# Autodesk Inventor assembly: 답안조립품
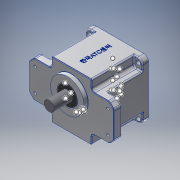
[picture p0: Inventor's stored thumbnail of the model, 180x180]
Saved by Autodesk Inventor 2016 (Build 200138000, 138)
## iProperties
Created: 2017-01
Part Number: 답안조립품
Material: 일반
Document SubType Name: Assembly
Designer: Owner
Author: Owner
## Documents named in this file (10)
- C:\Users\Owner\Desktop\470111V1013\답안조립품.iam
- C:\Users\Owner\Desktop\470111V1013\본체.ipt
- C:\Users\Owner\Desktop\470111V1013\메인축.ipt
- C:\Users\Owner\Desktop\470111V1013\베어링 608.ipt
- C:\Users\Owner\Desktop\470111V1013\베어링 6003.ipt
- C:\Users\Owner\Desktop\470111V1013\볼트 M4 x 10.ipt
- C:\Users\Owner\Desktop\470111V1013\서브축.ipt
- C:\Users\Owner\Desktop\470111V1013\오일실 8 22 7.ipt
- C:\Users\Owner\Desktop\470111V1013\오일실 17 32 8.ipt
- C:\Users\Owner\Desktop\470111V1013\커버.ipt
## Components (2 placed, 1 different names)
1. ISO 4762 M4 x 10:1
2. ISO 4762 M4 x 10:2
